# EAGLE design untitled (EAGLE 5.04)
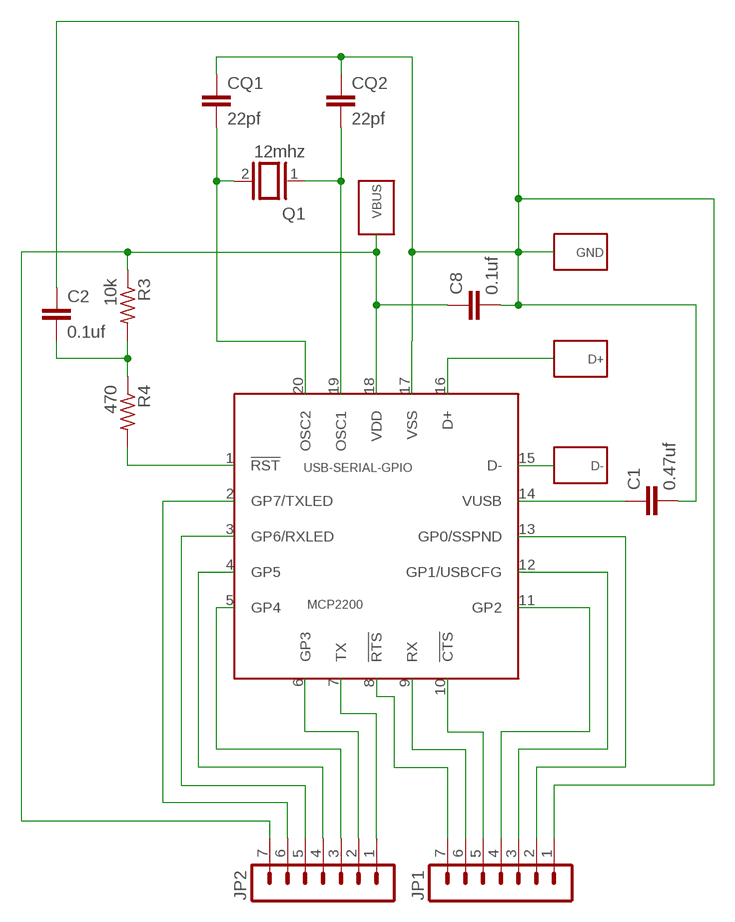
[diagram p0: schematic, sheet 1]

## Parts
C1  0.47uf  C-EUC1206  [C1206]
C2  0.1uf  C-EUC1206  [C1206]
C8  0.1uf  C-EUC1206  [C1206]
CQ1  22pf  C-EUC1206  [C1206]
CQ2  22pf  C-EUC1206  [C1206]
D+  WIREPAD-SMD-NO-VALUE  [WIREPAD-SMD]
D-  WIREPAD-SMD-NO-VALUE  [WIREPAD-SMD]
GND  WIREPAD-SMD-NO-VALUE  [WIREPAD-SMD]
JP1  MA07-1  [MA07-1]
JP2  MA07-1  [MA07-1]
Q1  12mhz  XTAL/S  [QS]
R3  10k  R-US_R1206  [R1206]
R4  470  R-US_R1206  [R1206]
USB-SERIAL-GPIO  MCP2200  [QFN20-5X5-POWERPAD]
VBUS  WIREPAD-SMD-NO-VALUE  [WIREPAD-SMD]

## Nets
GND: C1.2 C2.1 C8.2 CQ1.1 CQ2.1 GND.1(P) JP1.1 USB-SERIAL-GPIO.17(VSS)
N$1: CQ2.2 Q1.1 USB-SERIAL-GPIO.19(OSC1)
N$2: CQ1.2 Q1.2 USB-SERIAL-GPIO.20(OSC2)
N$3: C8.1 JP2.7 R3.1 USB-SERIAL-GPIO.18(VDD) VBUS.1(P)
N$4: D-.1(P) USB-SERIAL-GPIO.15(D-)
N$5: D+.1(P) USB-SERIAL-GPIO.16(D+)
N$6: JP1.2 USB-SERIAL-GPIO.13(GP0/SSPND)
N$7: C1.1 USB-SERIAL-GPIO.14(VUSB)
N$8: JP1.3 USB-SERIAL-GPIO.12(GP1/USBCFG)
N$9: R4.2 USB-SERIAL-GPIO.1(!RST)
N$10: C2.2 R3.2 R4.1
N$11: JP1.4 USB-SERIAL-GPIO.11(GP2)
N$12: JP1.5 USB-SERIAL-GPIO.10(!CTS)
N$13: JP1.6 USB-SERIAL-GPIO.9(RX)
N$14: JP1.7 USB-SERIAL-GPIO.8(!RTS)
N$15: JP2.1 USB-SERIAL-GPIO.7(TX)
N$16: JP2.2 USB-SERIAL-GPIO.6(GP3)
N$17: JP2.3 USB-SERIAL-GPIO.5(GP4)
N$18: JP2.4 USB-SERIAL-GPIO.4(GP5)
N$19: JP2.5 USB-SERIAL-GPIO.3(GP6/RXLED)
N$20: JP2.6 USB-SERIAL-GPIO.2(GP7/TXLED)

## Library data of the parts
C1 C2 C8 CQ1 CQ2 = resistor:C-EU: CAPACITOR, European symbol
D+ D- GND VBUS = trl:WIREPAD-SMD-NO-VALUE
JP1 JP2 = con-lstb:MA07-1: PIN HEADER
Q1 = special:XTAL/S: CRYSTAL
R3 R4 = resistor:R-US_: RESISTOR, American symbol
USB-SERIAL-GPIO = trl:MCP2200

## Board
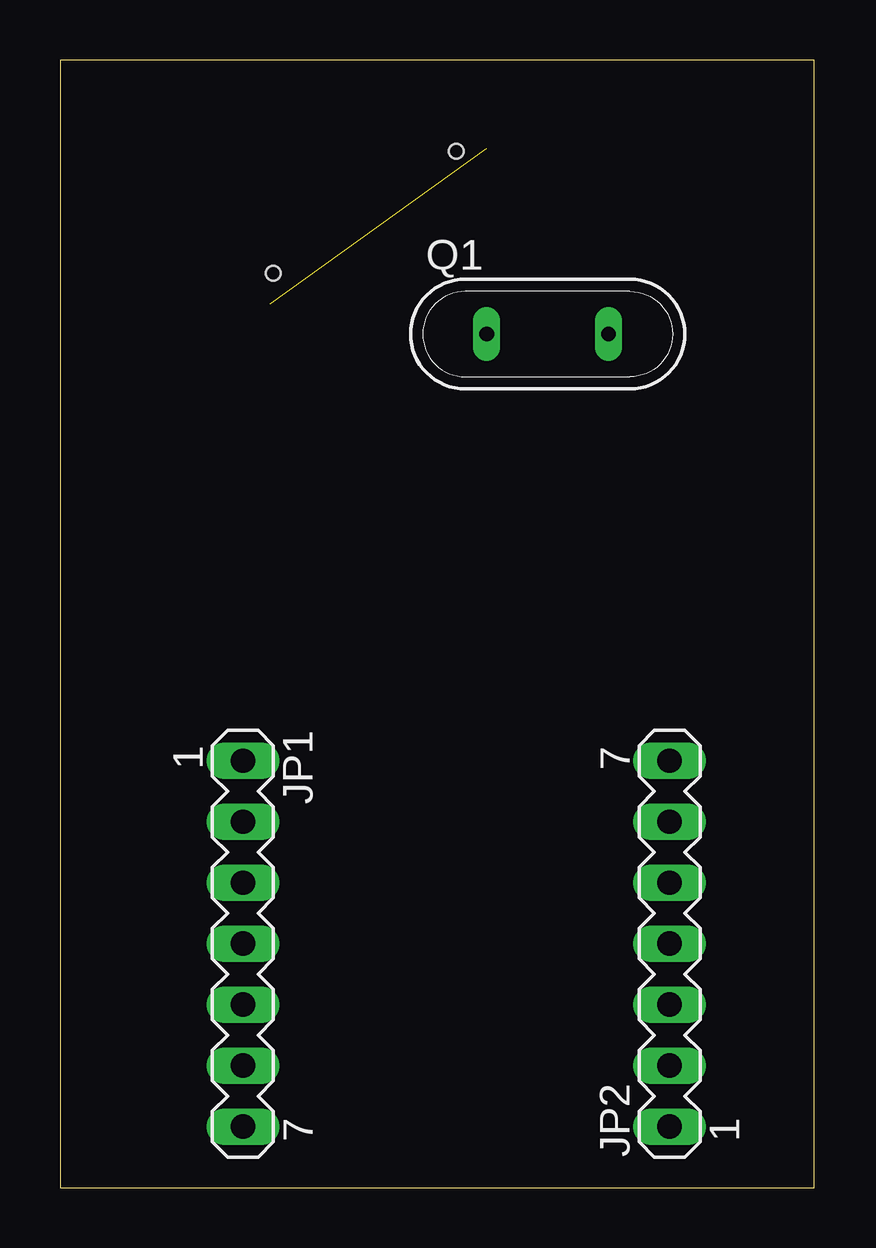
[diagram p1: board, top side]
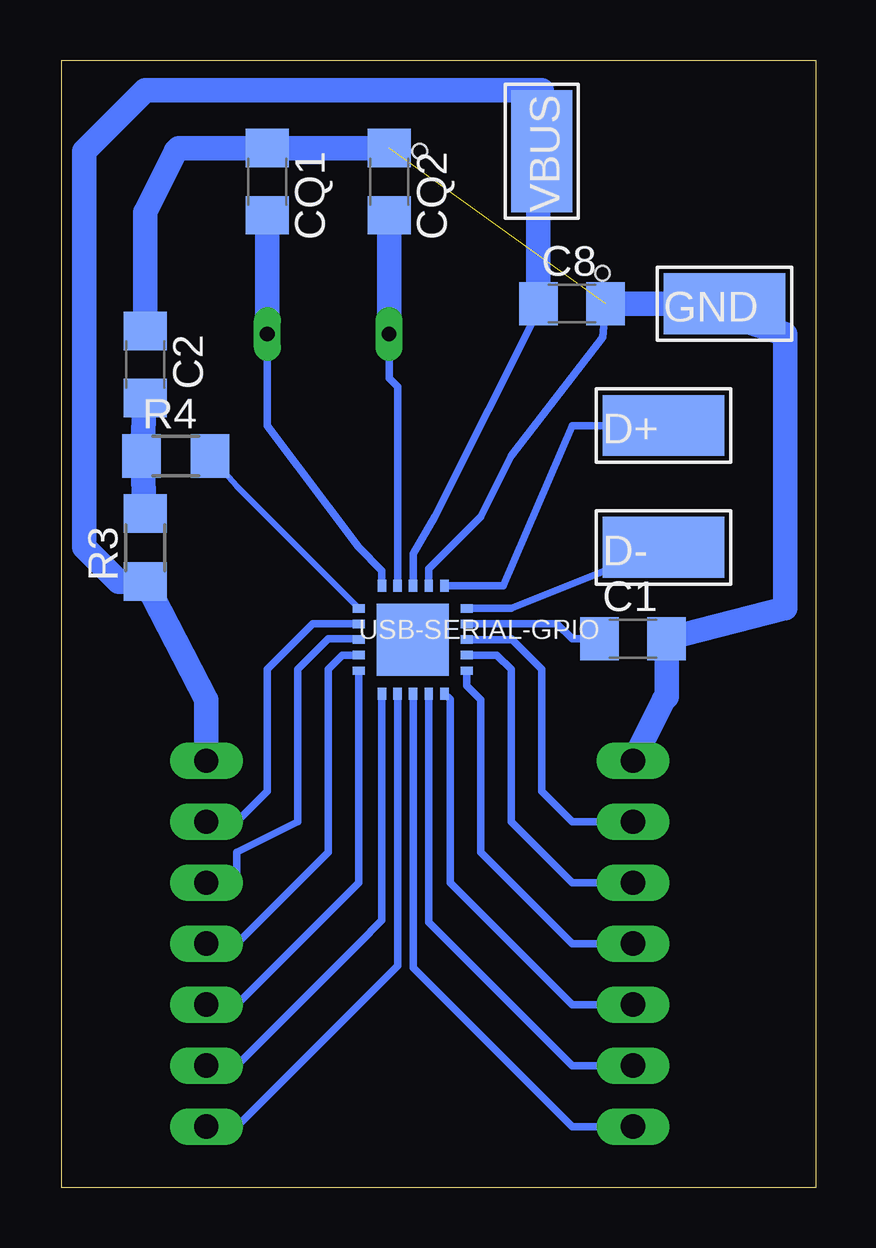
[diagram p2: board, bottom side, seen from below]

Size 31.42 x 46.98 mm. Coordinates in mm from the lower left corner, seen from the top.
Outline: 0,0 31.42,0 31.42,46.98 0,46.98 0,0
Copper layers (1*16): Top 0.035mm / dielectric 1.5mm / Bottom 0.035mm
Design rules "default": minimum track width 10mil, minimum drill 24mil, track to track 8mil, track to pad 8mil, pad to pad 8mil, via to via 8mil, smd to smd 8mil, copper to edge 40mil, drill to drill 8mil, minimum pad ring 10mil, minimum via ring 8mil, stop-mask expansion 4mil, vias tented up to drill 0mil, thermal gap 10mil
Holes 0.6 mm at 8.89,38.1 16.51,43.18

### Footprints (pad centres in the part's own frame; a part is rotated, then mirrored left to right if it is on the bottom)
C1206 = smd 1.6 x 1.8: 1 -1.4,0; 2 1.4,0
WIREPAD-SMD = smd 2.54 x 5.08: 1 0,0
MA07-1 = drill 1.016 long: 1 -7.62,0; 2 -5.08,0; 3 -2.54,0; 4 0,0; 5 2.54,0; 6 5.08,0; 7 7.62,0
QS = drill 0.61 long: 1 -2.54,0; 2 2.54,0
R1206 = smd 1.6 x 1.803: 1 -1.422,0; 2 1.422,0
QFN20-5X5-POWERPAD = smd 0.5 x 0.35: 1 -2.54,1.27; 2 -2.54,0.62; 3 -2.54,-0.03; 4 -2.54,-0.68; 5 -2.54,-1.33; 11 1.96,-1.33; 12 1.96,-0.68; 13 1.96,-0.03; 14 1.96,0.62; 15 1.96,1.27 | smd 0.35 x 0.5: 6 -1.57,-2.28; 7 -0.92,-2.28; 8 -0.27,-2.28; 9 0.38,-2.28; 10 1.03,-2.28; 16 1.03,2.22; 17 0.38,2.22; 18 -0.27,2.22; 19 -0.92,2.22; 20 -1.57,2.22 | smd 3 x 3: POWERPAD -0.29,-0.03

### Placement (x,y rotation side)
C1  7.62,22.86 0 bottom
C2  27.94,34.29 270 bottom
C8  10.16,36.83 0 bottom
CQ1  22.86,41.91 270 bottom
CQ2  17.78,41.91 270 bottom
D+  6.35,31.75 270 bottom
D-  6.35,26.67 270 bottom
GND  3.81,36.83 270 bottom
JP1  7.62,10.16 270 top
JP2  25.4,10.16 90 top
Q1  20.32,35.56 0 top
R3  27.94,26.67 90 bottom
R4  26.67,30.48 0 bottom
USB-SERIAL-GPIO  16.51,22.86 0 bottom
VBUS  11.43,43.18 0 bottom

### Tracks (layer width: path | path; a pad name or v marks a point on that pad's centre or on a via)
GND  (1 unrouted)
  Bottom 0.305: USB-SERIAL-GPIO.17 16.13,25.78 13.97,27.94 12.7,30.48 8.89,35.43 C8.2
  Bottom 1.016: CQ2.1 CQ1.1 26.54,43.31 26.67,43.18 27.94,40.64 27.94,38.23 C2.1 | 5.08,36.83 1.27,35.56 1.27,24.13 C1.2 6.22,20.45 6.35,20.32 JP1.1 | 5.08,36.83 C8.2 | 5.08,36.83 GND.1
N$1
  Bottom 0.305: USB-SERIAL-GPIO.19 17.43,33.37 17.78,33.72 Q1.1
  Bottom 1.016: CQ2.2 Q1.1
N$2
  Bottom 0.305: USB-SERIAL-GPIO.20 18.08,25.7 19.05,26.67 22.86,31.75 22.86,33.02 Q1.2
  Bottom 1.016: CQ1.2 Q1.2
N$3
  Bottom 0.305: USB-SERIAL-GPIO.18 16.78,26.4 15.88,27.94 11.43,36.83 C8.1
  Bottom 1.016: C8.1 11.56,41.78 VBUS.1 11.43,45.72 27.94,45.72 30.48,43.18 30.48,41.91 30.48,26.67 29.06,25.25 R3.1 25.4,20.32 JP2.7
N$4
  Bottom 0.305: USB-SERIAL-GPIO.15 12.7,24.13 D-.1
N$5
  Bottom 0.305: USB-SERIAL-GPIO.16 13.02,25.08 10.16,31.75 D+.1
N$6
  Bottom 0.305: USB-SERIAL-GPIO.13 12.73,22.83 12.7,22.86 11.43,21.59 11.43,16.51 10.16,15.24 JP1.2
N$7
  Bottom 0.305: USB-SERIAL-GPIO.14 13.32,23.48 10.79,23.5 10.16,22.86 C1.1
N$8
  Bottom 0.305: JP1.3 10.16,12.7 12.7,15.24 12.7,20.32 12.7,21.59 13.29,22.18 USB-SERIAL-GPIO.12
N$9
  Bottom 0.254: USB-SERIAL-GPIO.1 24.13,29.21 R4.2
N$10
  Bottom 0.254: R4.1 27.94,27.94 R4.1
  Bottom 1.016: C2.2 27.94,33.02 R4.1 27.94,27.94 R3.2
N$11
  Bottom 0.305: USB-SERIAL-GPIO.11 14.55,20.9 13.97,20.32 13.97,13.97 10.16,10.16 JP1.4
N$12
  Bottom 0.305: JP1.5 10.16,7.62 15.24,12.7 15.24,20.34 USB-SERIAL-GPIO.10
N$13
  Bottom 0.305: USB-SERIAL-GPIO.9 16.13,11.05 15.24,10.16 10.16,5.08 JP1.6
N$14
  Bottom 0.305: USB-SERIAL-GPIO.8 16.78,9.16 15.24,7.62 10.16,2.54 JP1.7
N$15
  Bottom 0.305: USB-SERIAL-GPIO.7 17.43,9.24 17.78,8.89 24.13,2.54 JP2.1
N$16
  Bottom 0.305: USB-SERIAL-GPIO.6 18.08,11.13 19.05,10.16 24.13,5.08 JP2.2
N$17
  Bottom 0.305: USB-SERIAL-GPIO.5 19.05,12.7 24.13,7.62 JP2.3
N$18
  Bottom 0.305: USB-SERIAL-GPIO.4 19.73,22.18 20.32,21.59 20.32,13.97 24.13,10.16 JP2.4
N$19
  Bottom 0.305: JP2.5 24.13,12.7 24.13,13.97 21.59,15.24 21.59,21.59 20.32,22.86 19.08,22.86 USB-SERIAL-GPIO.3
N$20
  Bottom 0.305: USB-SERIAL-GPIO.2 20.97,23.48 22.86,21.59 22.86,16.51 24.13,15.24 JP2.6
